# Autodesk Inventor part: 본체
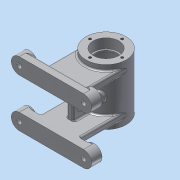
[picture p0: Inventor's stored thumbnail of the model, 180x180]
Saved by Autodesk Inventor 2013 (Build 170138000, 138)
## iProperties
Created: 2015-11
Part Number: 본체
Material: 알루미늄 6061
Document SubType Name: Modeling
Designer: user-11
Density: 2.71 g/cm^3
Mass: 359.522 g
Surface Area: 461.614 cm^2
Volume: 132.665 cm^3
Author: user-11
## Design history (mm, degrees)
sketch "스케치1"
  geometry: 1 further point
sketch "스케치2"
  geometry: 1 further point
sketch "스케치3"
  geometry: C1 r 25 at (0, 0); 1 further point
  constraints: 1 centre point, 1 coincident
  dimensions: "d0" = 50 diameter of C1
extrude "돌출1" new body sketch "스케치3" stored distance "d2" = 70; taper "d3" = 0 deg
node "작업 평면1"
sketch "스케치4"
  geometry: C1 r 21 at (0, 0); 1 further point
  constraints: 1 centre point, 1 coincident
  dimensions: "d4" = 42 diameter of C1
extrude "돌출2" cut sketch "스케치4" stored distance "d6" = 42; taper "d7" = 0 deg
sketch "스케치5"
  geometry: C1 r 25 at (0, 0) reference; C2 r 14 at (0, 0)
  constraints: 1 centre point, 1 coincident
  dimensions: "d8" = 28 diameter of C2
extrude "돌출3" cut sketch "스케치5" stored distance "d10" = 42; taper "d11" = 0 deg
sketch "스케치6"
  geometry: C1 r 14 at (0, 0) reference; C2 r 25 at (0, 0) reference; C3 r 16 at (0, 0)
  constraints: 1 centre point, 1 coincident
  dimensions: "d12" = 32 diameter of C3
extrude "돌출4" cut sketch "스케치6" distance "d14" = 12; taper "d15" = 0 deg
sketch "스케치7"
  geometry: C1 r 14 at (0, 0) reference; C2 r 25 at (0, 0) reference; C3 r 16 at (0, 0)
  constraints: 1 centre point, 1 coincident
  dimensions: "d16" = 32 diameter of C3
extrude "돌출5" cut sketch "스케치7" distance "d18" = 12; taper "d19" = 0 deg
node "작업 평면2"
node "작업 평면3"
sketch "스케치10"
  geometry: L1 (-4, 25)-(4, 25); L2 (4, 25)-(4, -25); L3 (4, -25)-(-4, -25); L4 (-4, -25)-(-4, 25); 1 further point
  constraints: 8 end point, 2 parallel, 1 horizontal, 1 perpendicular
  dimensions: "d36" = 4 distance from line of point (0, 0) L4; "d37" = 4 distance from line of point (0, 0) L2; "d38" = 50 distance of L1.end L2.end; "d39" = 25 distance from line of point (0, 0) L3
extrude "돌출8" join sketch "스케치10" stored distance "d40" = 13; taper "d41" = 0 deg
node "작업 평면4"
sketch "스케치11"
  geometry: L1 (-40, 30)-(40, 30); L2 (40, 30)-(40, -30); L3 (40, -30)-(-40, -30); L4 (-40, -30)-(-40, 30); L5 (-40, -20)-(40, -20); L6 (-40, -40)-(40, -40); L7 (40, 20)-(-40, 20); L8 (-40, 40)-(40, 40); A1 r 10 centre (-40, 30) between (-40, 40) and (-40, 20); A2 r 10 centre (40, 30) between (40, 20) and (40, 40); A3 r 10 centre (40, -30) between (40, -40) and (40, -20); A4 r 10 centre (-40, -30) between (-40, -20) and (-40, -40); 1 further point
  constraints: 16 end point, 8 point on circle, 5 point on line, 4 centre point, 4 coincident, 3 tangent, 2 parallel, 1 horizontal, 1 perpendicular
  dimensions: "d43" = 40 distance from line of point (0, 0) L4; "d44" = 80 distance of L1.start L1.end; "d45" = 30 distance from line of point (0, 0) L1; "d46" = 30 distance from line of point (0, 0) L3; "d47" = 20 diameter of A1; "d48" = 20 diameter of A2; "d49" = 20 diameter of A4; "d50" = 20 diameter of A3
extrude "돌출9" join sketch "스케치11" distance "d51" = 13; taper "d52" = 0 deg
sketch "스케치12"
  geometry: L1 (40, -20)-(-40, -20) reference; L2 (40, 20)-(-40, 20) reference; L3 (-40, 40)-(40, 40) reference; L4 (-25, 20)-(-25, 28); L5 (-25, 28)-(25, 28); L6 (25, 28)-(25, 20); L7 (-25, -20)-(-25, -28); L8 (-25, -28)-(25, -28); L9 (25, -28)-(25, -20); A1 r 10 centre (40, 30) between (40, 20) and (40, 40) reference; A2 r 10 centre (-40, 30) between (-40, 40) and (-40, 20) reference; 1 further point
  constraints: 12 end point, 5 perpendicular, 4 point on line, 1 parallel
  dimensions: "d53" = 25 distance from line of point (0, 0) L4; "d54" = 50 distance of L4.end L5.end; "d55" = 8 distance between parallel lines of L2 L5; "d56" = 25 distance from line of point (0, 0) L7; "d57" = 50 distance of L7.end L8.end; "d58" = 8 distance between parallel lines of L1 L8
extrude "돌출10" join sketch "스케치12" stored distance "d59" = 13; taper "d60" = 0 deg
sketch "스케치13"
  geometry: L1 (40, 20)-(-40, 20) reference; L2 (-40, 40)-(40, 40) reference; L3 (40, -20)-(-40, -20) reference; L4 (-40, -40)-(40, -40) reference; C1 r 10 at (40, -30); C2 r 10 at (-40, -30); C3 r 10 at (-40, 30); C4 r 10 at (40, 30); A1 r 10 centre (-40, -30) between (-40, -20) and (-40, -40) reference; A2 r 10 centre (40, -30) between (40, -40) and (40, -20) reference; A3 r 10 centre (40, 30) between (40, 20) and (40, 40) reference; A4 r 10 centre (-40, 30) between (-40, 40) and (-40, 20) reference; A5 r 10 centre (40, -30) between (40, -40) and (40, -20) reference; A6 r 10 centre (-40, -30) between (-40, -20) and (-40, -40) reference; 1 further point
  constraints: 4 centre point, 4 coincident, 4 concentric
extrude "돌출11" cut sketch "스케치13" distance "d61" = 3; taper "d62" = 0 deg
sketch "스케치14"
  geometry: L1 (40, 0)-(0, 0) reference; L2 (8.5, 10)-(31.5, 10); L3 (40, -23)-(60, -23) reference; L4 (20, 0)-(20, 10); L5 (12, 13.5)-(28, 13.5); L6 (28, 6.5)-(12, 6.5); A1 r 3.5 centre (12, 10) between (8.5, 10) and (12, 13.5); A2 r 3.5 centre (28, 10) between (31.5, 10) and (28, 13.5); 1 further point
  constraints: 8 end point, 6 point on circle, 2 centre point, 2 midpoint, 2 parallel, 2 point on line, 2 tangent, 1 perpendicular
  dimensions: "d66" = 33 distance between parallel lines of L3 L2; "d67" = 11.5 distance from line of L4 L2.start; "d68" = 11.5 distance from line of L4 L2.end; "d70" = 7 diameter of A1; "d71" = 7 diameter of A2
extrude "돌출12" cut sketch "스케치14" stored distance "d72" = 3; taper "d73" = 0 deg
sketch "스케치15"
  geometry: L1 (25, 20)-(25, 28) reference; L2 (25, 28)-(-25, 28) reference; L3 (-25, 28)-(-25, 20) reference; L4 (25, 20)-(-25, 20) reference; 1 further point
extrude "돌출13" join sketch "스케치15" distance "d74" = 3; taper "d75" = 0 deg
sketch "스케치16"
  geometry: L1 (25, -28)-(25, -20) reference; L2 (-25, -20)-(25, -20) reference; L3 (-25, -20)-(-25, -28) reference; L4 (-25, -28)-(25, -28) reference; 1 further point
extrude "돌출14" join sketch "스케치16" distance "d76" = 3; taper "d77" = 0 deg
sketch "스케치17"
  geometry: C1 r 10 at (0, 0) reference; C2 r 6 at (0, 0); C3 r 10 at (0, -60) reference; C4 r 10 at (80, -60) reference; C5 r 10 at (80, 0) reference; C6 r 6 at (80, 0); C7 r 6 at (80, -60); C8 r 6 at (0, -60); 1 further point
  constraints: 4 centre point, 4 coincident
  dimensions: "d78" = 12 diameter of C2; "d80" = 12 diameter of C6; "d81" = 12 diameter of C7; "d82" = 12 diameter of C8
extrude "돌출15" cut sketch "스케치17" distance "d83" = 4; taper "d84" = 0 deg
sketch "스케치18"
  geometry: C1 r 6 at (0, 0) reference; C2 r 6 at (-80, 0) reference; C3 r 6 at (-80, -60) reference; C4 r 6 at (0, -60) reference; C5 r 3 at (0, -60); C6 r 3 at (0, 0); C7 r 3 at (-80, 0); C8 r 3 at (-80, -60); 1 further point
  constraints: 4 centre point, 4 coincident
  dimensions: "d85" = 6 diameter of C8; "d87" = 6 diameter of C7; "d88" = 6 diameter of C6; "d89" = 6 diameter of C5
extrude "돌출16" cut sketch "스케치18" stored distance "d90" = 4; taper "d91" = 0 deg
node "작업 평면5"
sketch "스케치19"
  geometry: C1 r 5 at (0, 0); 1 further point
  constraints: 1 centre point, 1 coincident
  dimensions: "d93" = 10 diameter of C1
extrude "돌출17" join sketch "스케치19" stored distance "d95" = 4; taper "d96" = 0 deg
sketch "스케치20"
  geometry: L1 (0, 0)-(14, -24.249); L2 (0, 0)-(0, -25); L3 (14, -24.249)-(8.804, -27.249); L4 (8.804, -27.249)-(5.902, -22.222); L5 (5.902, -22.222)-(11.098, -19.222); A1 r 25 centre (0, 0) between (-25, 0) and (25, 0) reference
  constraints: 10 end point, 3 perpendicular, 1 point on circle, 1 point on line
  dimensions: "d97" = 30 deg angle of L2 L1; "d98" = 28 distance of L1.start L1.end; "d99" = 12 diameter of L4 L1
revolve "회전1" sketch "스케치20" stored, may be unused: angle "d100" = 90 deg
sketch "스케치21" dims "d101" = 40
  geometry: C1 r 25 at (0, 0) reference; C2 r 1.506 at (0, 20); 1 further point
  constraints: 1 centre point, 1 coincident, 1 vertical alignment, 2 other
hole "구멍1" sketch "스케치21" at (0, 20) diameter "d103" = 3.242; stored, may be unused: countersink angle "d107" = 90 deg, drill point angle "d109" = 118 deg; dims "d104" = 8, "d105" = 4, "d106" = 2, "d108" = 10
sketch "스케치22"
  geometry: C1 r 5 at (0, 0) reference
hole "구멍2" sketch "스케치22" at (0, 0) diameter "d113" = 5.188; stored, may be unused: countersink angle "d117" = 90 deg, drill point angle "d119" = 0 deg; dims "d114" = 10, "d115" = 4, "d116" = 2, "d118" = 10
sketch "스케치23"
  geometry: C1 r 6 at (0, 0) reference
hole "구멍3" sketch "스케치23" at (0, 0) diameter "d120" = 5.188; stored, may be unused: countersink angle "d124" = 90 deg, drill point angle "d126" = 0 deg; dims "d121" = 10, "d122" = 4, "d123" = 2, "d125" = 10
fillet "모깎기1" dims "d127" = 0.3
fillet "모깎기2" dims "d128" = 2
fillet "모깎기3" dims "d129" = 2
fillet "모깎기4" dims "d130" = 2
fillet "모깎기5" dims "d131" = 2
fillet "모깎기6" dims "d132" = 2
fillet "모깎기7" dims "d133" = 2
fillet "모깎기8" dims "d134" = 2
fillet "모깎기9" dims "d135" = 3
node "작업 평면6"
sketch "스케치24"
  geometry: L1 (-3.002, -20.739)-(-3.002, 20.739); L2 (-3.002, 20.739)-(3.002, 20.739); L3 (3.002, 20.739)-(3.002, -20.739); L4 (3.002, -20.739)-(-3.002, -20.739); L5 (0, -20.739)-(0, 20.739); L6 (-3.002, 0)-(3.002, 0); 1 further point
  constraints: 4 end point, 4 midpoint, 2 other
  dimensions: "d137" = 0 distance from line of point (0, 0) L5; "d138" = 0 distance from line of point (0, 0) L6
feature "엠보싱1" sketch "스케치24" dims "d139" = 0.5, "d140" = 0
node "솔리드1"
pattern_circular "원형 패턴1" dims angle "d111" = 360 deg
mirror "대칭1"
node "투영된 루프3"
node "투영된 루프4"
node "투영된 루프5"
node "투영된 루프6"
node "투영된 루프7"
node "투영된 루프8"
node "투영된 루프9"
node "투영된 루프10"
other parameters: "d20" = -68, "d31" = -45, "d42" = -68, "d92" = 96, "d136" = -134.5
